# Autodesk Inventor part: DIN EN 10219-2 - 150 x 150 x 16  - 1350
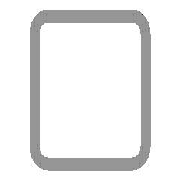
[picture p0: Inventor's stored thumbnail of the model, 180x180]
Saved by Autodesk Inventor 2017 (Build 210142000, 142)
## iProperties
_CCFamilyMember: 76
_CCFamilyDisplayName: DIN EN 10219-2 (Square Hollow Section - Cold Formed) - Cold formed welded structural hollow sections of non-alloy and fine grain structural steel
_FrameMemberDoc: Frame Member File
_Version: 15.0.0
_GetPNFromCC: 1
Created: 2016-02
Part Number: DIN EN 10219-2 - 150 x 150 x 16  - 1350
Material: Steel, Mild
Description: Cold formed welded structural hollow sections of non-alloy and fine grain structural steel
Document SubType Name: Modeling
Standard: DIN
Designer: iusti
Standard Revision: 2006-07
Standards Organization: DIN
Language: en-US
Size Designation: 150 x 150 x 16
Categories: <MemberInstance><Categories><Category DisplayName="Structural Shapes" InternalName="089c4875-fa83-4c05-b084-43b9cc11f5ed" Mnemonic="GRDR"><CategoryParameter Dis
Stock Number: 150 x 150 x 16
Mass: 79240 g
Surface Area: 12767.4 cm^2
Volume: 10094.3 cm^3
Density: 7.85 g/cm^3
Appearance: Semi-Polished
IsCustomPart: 1
G_W: 150.000 mm
G_H: 150.000 mm
G_L: 1350.000 mm
+452AD748-903E-47FB-AD5B-3293C161C6CB+CUTDETAIL2: Cut
+C5B3B437-76DA-41F1-9D90-B2EA784F79B1+CUTDETAIL3: Cut
Author: iusti
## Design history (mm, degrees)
node "Start plane"
node "End plane"
sketch "Sketch"
  geometry: L1 (-75, -27)-(-75, 27); L2 (-27, 75)-(27, 75); L3 (75, 27)-(75, -27); L4 (27, -75)-(-27, -75); L5 (-27, 59)-(27, 59); L6 (59, 27)-(59, -27); L7 (27, -59)-(-27, -59); L8 (-59, -27)-(-59, 27); L9 (0, 153.918)-(0, -153.918) reference; L10 (-153.918, 0)-(153.918, 0) reference; A1 r 48 centre (-27, -27) between (-75, -27) and (-27, -75); A2 r 48 centre (-27, 27) between (-27, 75) and (-75, 27); A3 r 48 centre (27, 27) between (75, 27) and (27, 75); A4 r 48 centre (27, -27) between (27, -75) and (75, -27); A5 r 32 centre (-27, 27) between (-27, 59) and (-59, 27); A6 r 32 centre (27, 27) between (59, 27) and (27, 59); A7 r 32 centre (27, -27) between (27, -59) and (59, -27); A8 r 32 centre (-27, -27) between (-59, -27) and (-27, -59)
  constraints: 16 end point, 16 point on circle, 8 centre point, 8 tangent, 4 parallel, 3 equal radius, 2 perpendicular, 7 other
  dimensions: "d7" = 48 radius of A1 (= G_IR); "d10" = 150 distance between parallel lines of L2 L4 (= G_H); "d11" = 150 distance between parallel lines of L1 L3 (= G_W); "d12" = 16 distance between parallel lines of L3 L6 (= G_T); "d15" = 75 distance between parallel lines of L2 L10 (= 0.5 x d10); "d16" = 75 distance between parallel lines of L9 L3 (= 0.5 x d11)
extrude "Body" new body sketch "Sketch" stored distance "d3" = 1350 (= G_L); taper "d4" = 0 deg
node "Driven Length"
  sketch "Sketch3"
    geometry: L1 (0, 0)-(10, 0) reference
    constraints: 2 end point, 1 horizontal
  workplane "Work Plane3"
  sketch "Sketch4"
    geometry: L1 (-2, 75)-(12, 75) reference; L2 (-2, 1425)-(12, 1425) reference
    dimensions: "d18" = 1350 distance between parallel lines of L1 L2 (derived)
workplane "Work Plane5"
split "Split2"
workplane "Work Plane6"
split "Split3"
body "Solid1"
other parameters: "G_W" = 150 [user parameter; used in 1 equation term], "G_H" = 150 [user parameter; used in 1 equation term], "G_T" = 16 [user parameter; used in 1 equation term], "G_IR" = 48 [user parameter; used in 1 equation term], "G_L" = 1350 (= d18) [user parameter; used in 1 equation term], "G_OFFSET_START" = -75 [user parameter; used in 1 equation term], "G_OFFSET_END" = -75 [user parameter; used in 1 equation term], "d13" = 75 (= -G_OFFSET_START), "d14" = 1425 (= G_OFFSET_END + B_L), "d17" = 90 deg
